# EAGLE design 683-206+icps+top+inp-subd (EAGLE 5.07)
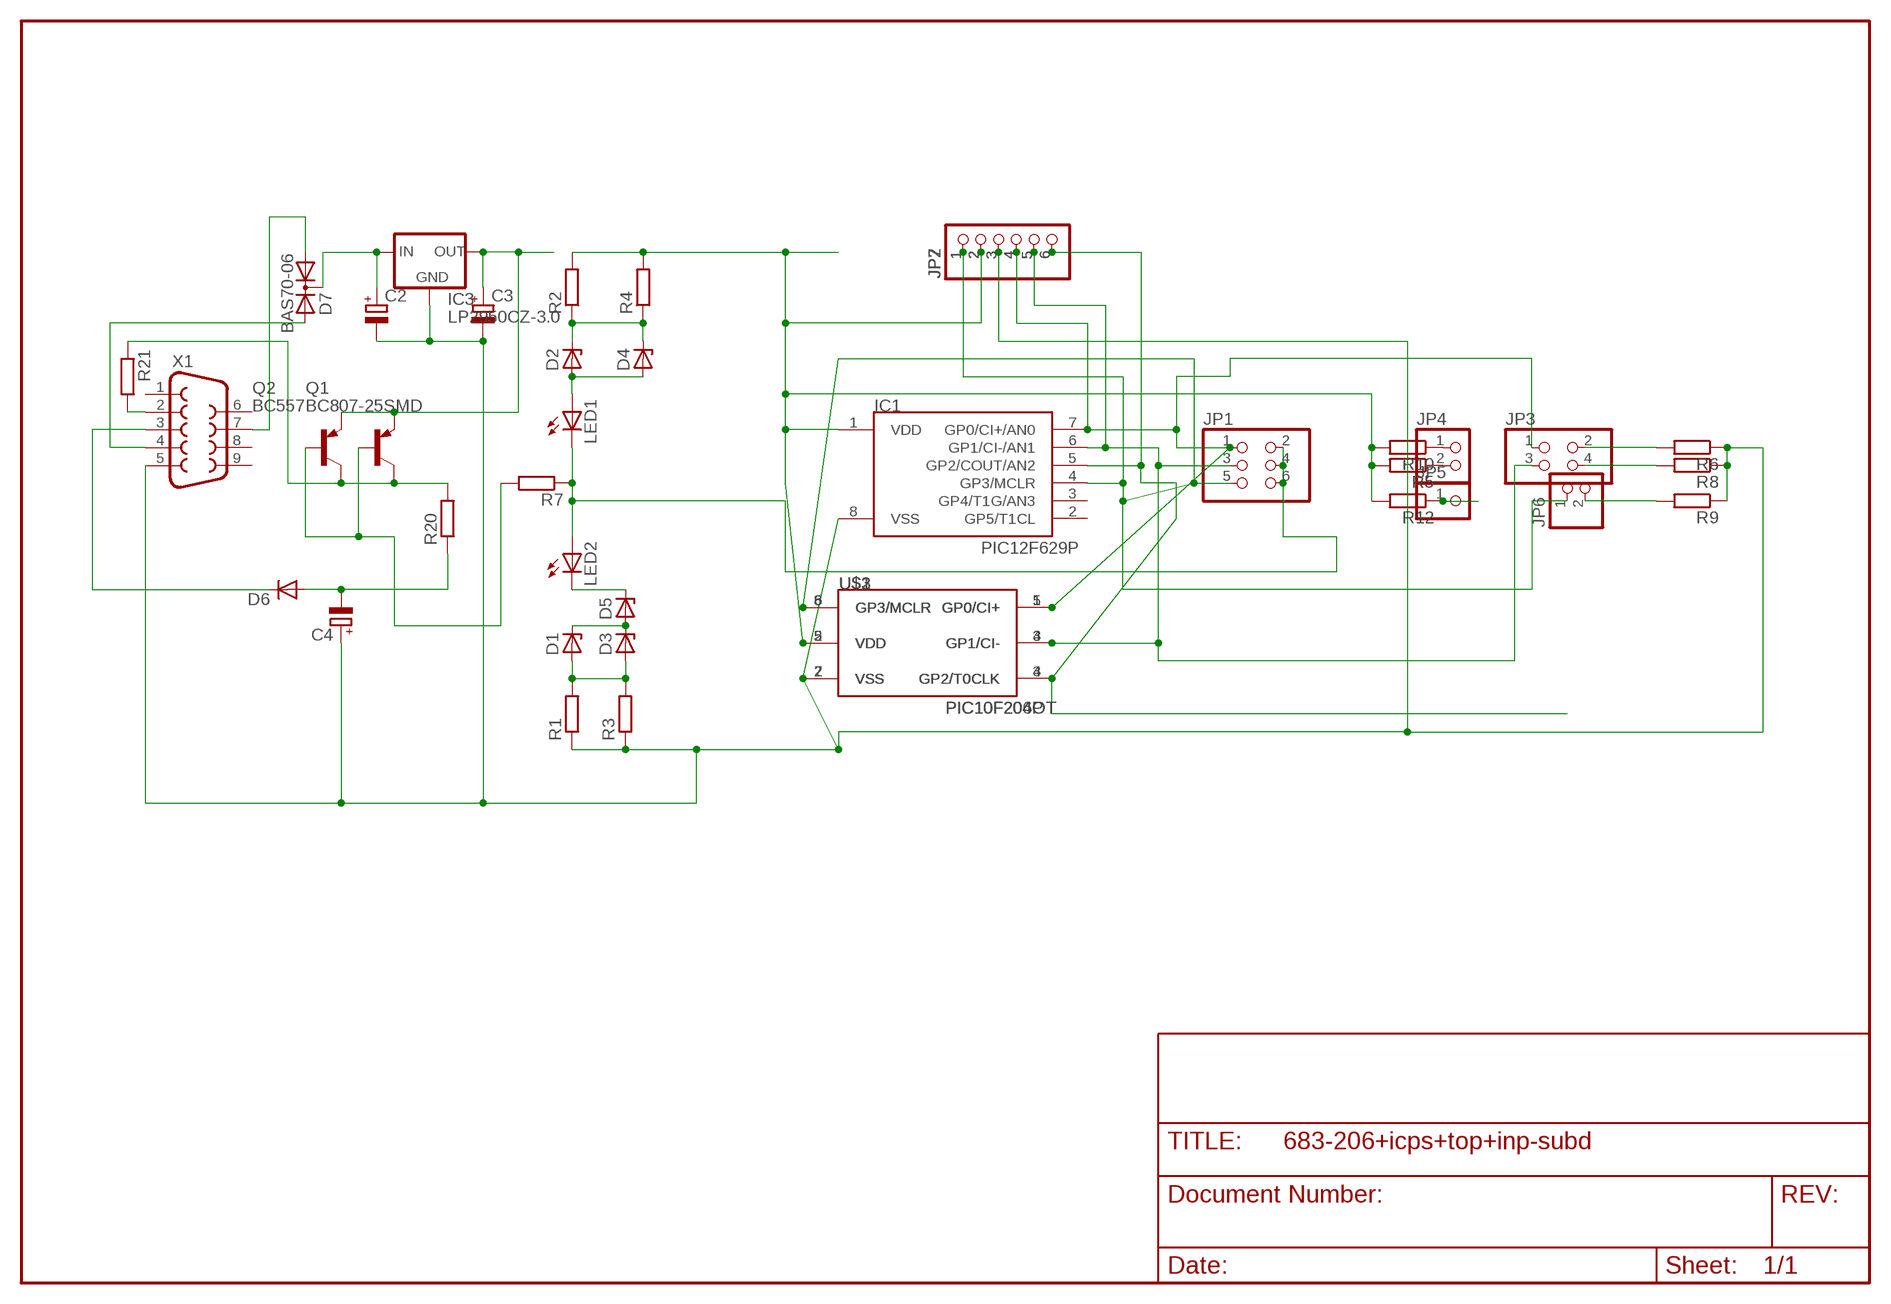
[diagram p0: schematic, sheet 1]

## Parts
C2  CPOL-EUE2-5  [E2-5]
C3  CPOL-EUE2.5-5  [E2,5-5]
C4  CPOL-EUE2.5-5  [E2,5-5]
D1  ZENER-DIODESOT23  [SOT23]
D2  ZENER-DIODESOT23  [SOT23]
D3  ZENER-DIODEZD-2.5  [ZDIO-2.5]
D4  ZENER-DIODEZD-2.5  [ZDIO-2.5]
D5  ZENER-DIODESOT23  [SOT23]
D6  DIODE-D-5  [D-5]
D7  BAS70-06  [SOT23]
IC1  PIC12F629P  [DIL8]
IC3  LP2950CZ-3.0  [TO92]
JP1  PINHD-2X3  [2X03]
JP2  PINHD-1X6  [1X06]
JP3  PINHD-2X2  [2X02]
JP4  PINHD-1X2  [1X02]
JP5  PINHD-1X1  [1X01]
JP6  PINHD-1X2  [1X02]
JP7  PINHD-1X6  [1X06]
LED1  LED5MM  [LED5MM]
LED2  LED5MM  [LED5MM]
Q1  BC807-25SMD  [SOT23-BEC]
Q2  BC557  [TO92-EBC]
R1  R-EU_0204/2V  [0204V]
R2  R-EU_0204/2V  [0204V]
R3  R-EU_R1206  [R1206]
R4  R-EU_R1206  [R1206]
R5  R-EU_R1206  [R1206]
R6  R-EU_R1206  [R1206]
R7  R-EU_R0805  [R0805]
R8  R-EU_R1206  [R1206]
R9  R-EU_R1206  [R1206]
R10  R-EU_R1206  [R1206]
R12  R-EU_R1206  [R1206]
R20  R-EU_R0805  [R0805]
R21  R-EU_R0805  [R0805]
U$1  PIC10F206P  [DIL8]
U$2  PIC10F204OT  [SOT23-6]
U$3  PIC10F204OT  [SOT23-6]
X1  F09H  [F09H]

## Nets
N$1: IC1.6(GP1/CI-/AN1) JP1.3 JP2.5 JP3.3 JP7.5 U$1.4(GP1/CI-) U$2.3(GP1/CI-) U$3.3(GP1/CI-)
N$2: D1.3(C) D3.C D5.1(A)
N$3: D1.1(A) D3.A R1.2 R3.2
N$4: JP1.2 JP1.4 JP1.6 LED1.K(C) LED2.A R7.1
N$5: D7.2(A2) X1.4
N$6: IC1.1(VDD) JP2.2 JP7.2 R2.2 R4.2 R5.2 R10.2 R12.2 U$1.2(VDD) U$2.5(VDD) U$3.5(VDD)
N$7: D2.1(A) D4.A LED1.A
N$8: D2.3(C) D4.C R2.1 R4.1
N$9: IC1.5(GP2/COUT/AN2) JP2.6 JP7.6 U$1.3(GP2/T0CLK) U$2.4(GP2/T0CLK) U$3.4(GP2/T0CLK)
N$10: IC1.4(GP3/MCLR) JP1.5 JP2.1 JP6.1 JP7.1 U$1.8(GP3/MCLR) U$2.6(GP3/MCLR) U$3.6(GP3/MCLR)
N$11: D5.3(C) LED2.K(C)
N$12: Q1.B Q2.B R7.2
N$13: IC1.7(GP0/CI+/AN0) JP1.1 JP2.4 JP3.1 JP7.4 U$1.5(GP0/CI+) U$2.1(GP0/CI+) U$3.1(GP0/CI+)
N$15: JP4.2 R5.1
N$16: JP4.1 R10.1
N$18: JP5.1 R12.1
N$19: D7.1(A1) X1.7
N$22: JP6.2 R9.2
N$24: JP3.4 R8.2
N$25: JP3.2 R6.2
N$33: D6.C X1.3
N$36: Q1.C Q2.C R20.2 R21.1
N$37: C4.- D6.A R20.1
N$38: R21.2 X1.2
N$40: C2.+ D7.3(C) IC3.3(IN)
VDD: C3.+ IC3.1(OUT) Q1.E Q2.E
VSS: C2.- C3.- C4.+ IC1.8(VSS) IC3.2(GND) JP2.3 JP7.3 R1.1 R3.1 R6.1 R8.1 R9.1 U$1.7(VSS) U$2.2(VSS) U$3.2(VSS) X1.5
Unconnected: IC1.2(GP5/T1CL) IC1.3(GP4/T1G/AN3) X1.1 X1.6 X1.8 X1.9

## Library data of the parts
C2-C4 = rcl-2:CPOL-EU: POLARIZED CAPACITOR, European symbol
D1-D5 = diode-1:ZENER-DIODE: Z-Diode
D6 = diode-1:DIODE-: DIODE
D7 = diode-1:BAS70-06: Silicon Schottky Diodes General-purpose diode for high-speed switching
IC1 = microchip-5:PIC12F6*: uPC nW 1k Program Flash memory 2x Timer Comparator 10b A/D converter/ 4xIN
IC3 = v-reg:LP2950?*: Source: http://cache.national.com/ds/LP/LP2950.pdf
JP1 = pinhead:PINHD-2X3: PIN HEADER
JP2 JP7 = pinhead:PINHD-1X6: PIN HEADER
JP3 = pinhead(2):PINHD-2X2: PIN HEADER
JP4 JP6 = pinhead(2):PINHD-1X2: PIN HEADER
JP5 = pinhead(2):PINHD-1X1: PIN HEADER
LED1 LED2 = led:LED: LED
Q1 = transistor-pnp:BC807*: PNP Transistror
Q2 = transistor-pnp:BC557*: PNP Transistror
R1-R10 R12 R20 R21 = rcl-2:R-EU_: RESISTOR, European symbol
U$1-U$3 = microchip-5:PIC10F2*: uPC nW 0,25/0,5k Program Flash memory Comparator
X1 = con-subd:F09: SUB-D

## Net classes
0 default: width 0.3 mm, drill 0.6 mm, clearance 0.2 mm
1 power: width 0.4 mm, drill 0.6 mm, clearance 0.2 mm

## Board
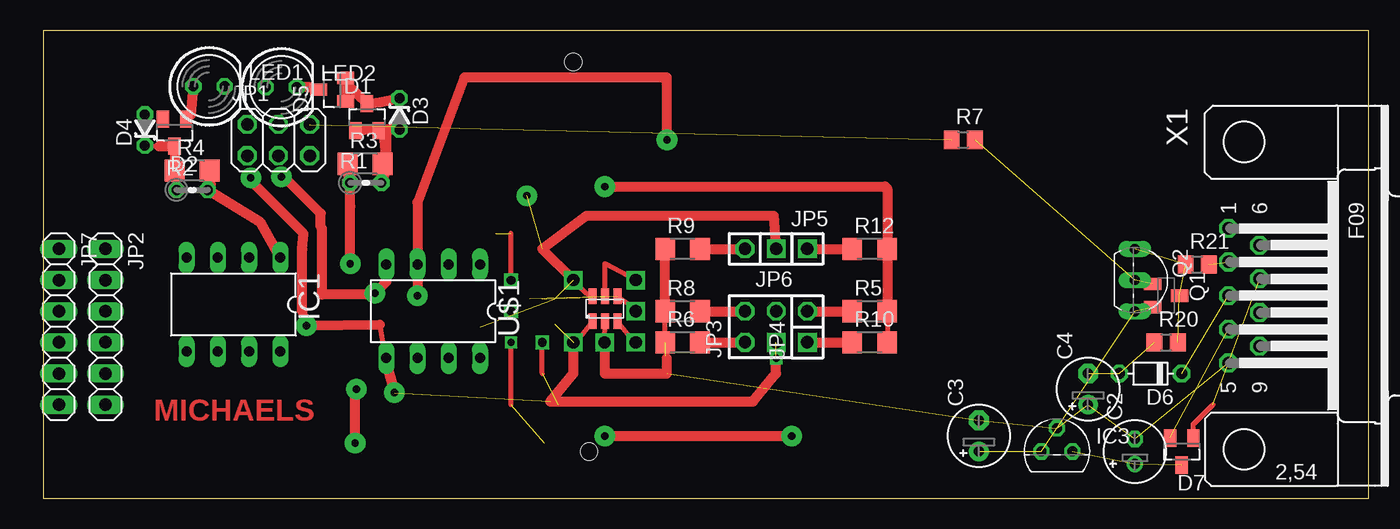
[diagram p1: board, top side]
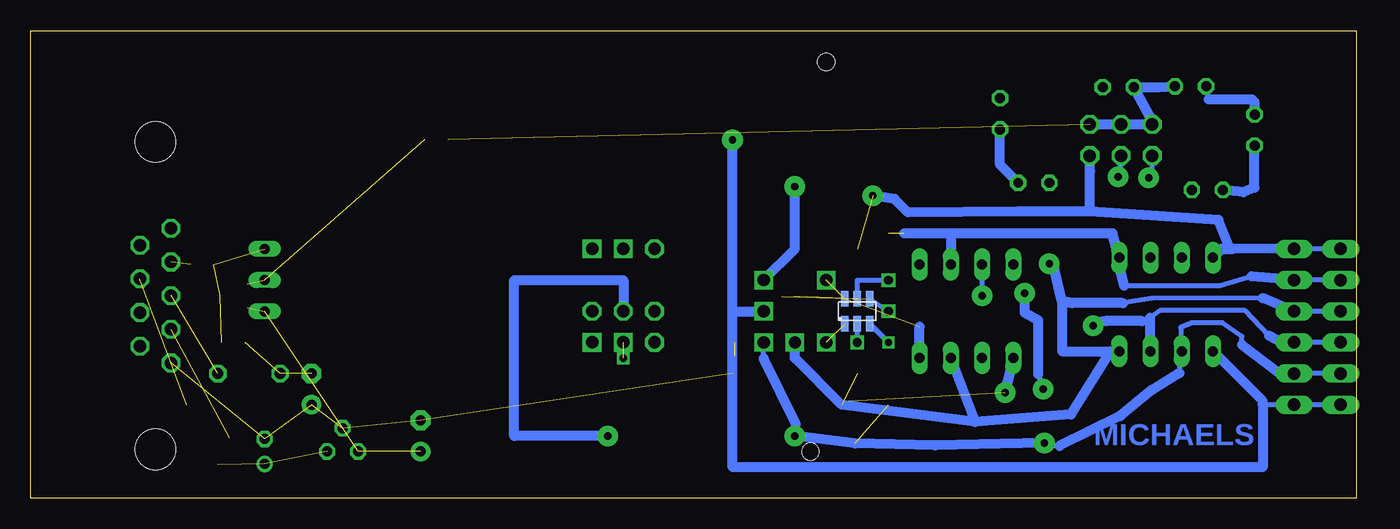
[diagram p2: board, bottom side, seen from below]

Size 107.95 x 38.1 mm. Coordinates in mm from the lower left corner, seen from the top.
Outline: 0,0 107.95,0 107.95,38.1 0,38.1 0,0
Copper layers (1*16): Top 0.035mm / dielectric 1.5mm / Bottom 0.035mm
Design rules "default": minimum track width 10mil, minimum drill 24mil, track to track 8mil, track to pad 8mil, pad to pad 8mil, via to via 8mil, smd to smd 8mil, copper to edge 40mil, drill to drill 8mil, minimum pad ring 10mil, minimum via ring 8mil, stop-mask expansion 4mil, vias tented up to drill 0mil, thermal gap 10mil
Holes 1.4 mm at 44.45,3.81 43.18,35.56

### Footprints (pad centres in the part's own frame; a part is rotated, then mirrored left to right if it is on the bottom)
E2-5 = drill 0.813 pad 1.27 round: + -1.016,0 | drill 0.813 pad 1.27 octagon: - 1.016,0
E2,5-5 = drill 0.813 pad 1.6 round: + -1.27,0 | drill 0.813 pad 1.6 octagon: - 1.27,0
SOT23 = smd 1 x 1.4: 1 -0.95,-1.1; 2 0.95,-1.1; 3 0,1.1
ZDIO-2.5 = drill 0.813 octagon: A 1.27,0; C -1.27,0
D-5 = drill 0.9 octagon: A 2.54,0; C -2.54,0
DIL8 = drill 0.813 long: 1 -3.81,-3.81; 2 -1.27,-3.81; 3 1.27,-3.81; 4 3.81,-3.81; 5 3.81,3.81; 6 1.27,3.81; 7 -1.27,3.81; 8 -3.81,3.81
TO92 = drill 0.813 octagon: 1 -1.27,0; 2 0,1.905; 3 1.27,0
2X03 = drill 1.016 octagon: 1 -2.54,-1.27; 2 -2.54,1.27; 3 0,-1.27; 4 0,1.27; 5 2.54,-1.27; 6 2.54,1.27
1X06 = drill 1.016 long: 1 -6.35,0; 2 -3.81,0; 3 -1.27,0; 4 1.27,0; 5 3.81,0; 6 6.35,0
2X02 = drill 1.016 square: 1 -1.27,-1.27 | drill 1.016 octagon: 2 -1.27,1.27; 3 1.27,-1.27; 4 1.27,1.27
1X02 = drill 1.016 square: 1 -1.27,0 | drill 1.016 octagon: 2 1.27,0
1X01 = drill 1.016 square: 1 0,0
LED5MM = drill 0.813 octagon: A -1.27,0; K 1.27,0
SOT23-BEC = smd 1 x 1.4: B -0.95,-1.1; C 0,1.1; E 0.95,-1.1
TO92-EBC = drill 0.813 long: B 0,-1.27; C -2.54,-1.27; E 2.54,-1.27
0204V = drill 0.813 octagon: 1 -1.27,0; 2 1.27,0
R1206 = smd 1.6 x 1.803: 1 -1.422,0; 2 1.422,0
R0805 = smd 1.3 x 1.5: 1 -0.95,0; 2 0.95,0
SOT23-6 = smd 0.635 x 1.27: 1 -1.016,-1.016; 2 0,-1.016; 3 1.016,-1.016; 4 1.016,1.016; 5 0,1.016; 6 -1.016,1.016
F09H = drill 1.016 octagon: 1 -5.486,-1.27; 2 -2.743,-1.27; 3 0,-1.27; 4 2.743,-1.27; 5 5.486,-1.27; 6 -4.115,1.27; 7 -1.372,1.27; 8 1.372,1.27; 9 4.115,1.27 | hole 3.302: -12.522,0; 12.522,0

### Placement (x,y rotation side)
C2  88.9,3.81 90 top
C3  76.2,5.08 90 top
C4  85.09,8.89 90 top
D1  26.36,31.06 0 top
D2  10.7,29.79 180 top
D3  29.01,31.33 270 top
D4  8.28,30 90 top
D5  23.52,33.29 90 top
D6  90.17,10.16 180 top
D7  92.71,3.81 180 top
IC1  15.49,15.79 180 top
IC3  82.55,3.81 0 top
JP1  19.16,29.19 0 top
JP2  5.08,13.97 270 top
JP3  58.42,13.97 90 top
JP4  62.23,13.97 90 top
JP5  62.23,20.32 0 top
JP6  58.42,20.32 180 top
JP7  1.27,13.97 270 top
LED1  13.5,33.56 0 top
LED2  19.39,33.49 0 top
Q1  91.44,16.51 270 top
Q2  90.17,17.78 270 top
R1  26.27,25.7 0 top
R2  12.13,25.13 0 top
R3  26.22,27.25 0 top
R4  12.13,26.69 0 top
R5  67.31,15.24 0 top
R6  52.07,12.7 0 top
R7  74.93,29.21 0 top
R8  52.07,15.24 0 top
R9  52.07,20.32 0 top
R10  67.31,12.7 0 top
R12  67.31,20.32 0 top
R20  91.44,12.7 0 top
R21  93.98,19.05 0 top
U$1  31.75,15.24 180 top
U$2  45.75,15.44 0 top
U$3  40.64,15.24 0 bottom
X1  97.79,16.51 270 top

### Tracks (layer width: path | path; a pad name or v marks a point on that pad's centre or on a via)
N$1  (via drill 0.6, 0.6 pad 1.68, 1)  (1 unrouted)
  Top 0.406: U$2.3 47.77,13.19 v48.26,12.7 | 25.4,8.6 v25.5,8.9 | v27,16.7 26.9,16.6 | 19.6,26.2 v19.4,26.2 | 22.7,22.01 22.6,22.11 | 38.1,7.62 v38.1,12.7
  Top 0.813: 22.7,22.01 22.7,16.6 26.9,16.6 | v25.4,4.5 25.4,8.6 | v45.72,5.08 v60.96,5.08 | U$1.4 27.94,17.64 v27,16.7 | 19.6,26.2 22.6,23.2 22.6,22.11
  Bottom 0.406: 6.27,10.16 JP2.5 JP7.5 | 9.31,12.5 9.31,13.2 10.91,14.3 13.41,14.3 14.31,13.9 14.31,12.07 IC1.6 14.41,11.79 14.41,10.2 | 48.26,11.43 v48.26,12.7 | v45.72,5.08 45.72,6.03 45.65,6.06 | v25.5,8.9 25.9,10.1 | 24.17,4.26 25.46,4.26 v25.4,4.5 | JP1.3 19.16,26.44 v19.4,26.2 | v38.1,12.7 U$3.3
  Bottom 0.813: 6.27,10.16 9.31,12.5 | 45.65,6.06 48.26,11.43 | 24.17,4.26 19.21,6.7 16.71,8.8 14.41,10.2 | 25.9,10.1 25.9,14.5 27,15.11 v27,16.7 | JP3.3 59.69,17.78 68.58,17.78 68.58,5.08 v60.96,5.08 | v25.4,4.5 34.3,4.3 40.82,4.47 v45.72,5.08
N$2
  Top 0.813: D5.1 24.69,33.8 D1.3 27.4,32.26 D3.C
N$3
  Top 0.813: 27.74,26.56 R3.2 27.94,26.7 R1.2 | D1.1 27.74,30.06 27.94,27.94 27.94,30.06 D3.A
  Bottom 0.813: D3.A 29.01,27.18 R1.2
N$4  (1 unrouted)
  Bottom 0.406: JP1.2 16.62,30.72
  Bottom 0.813: LED1.K 16.11,33.49 LED2.A 16.62,30.72 | JP1.2 JP1.4 JP1.6
N$5  (1 unrouted)
N$6  (via drill 0.6 pad 1.68, 0.7 pad 0.61, 1)  (2 unrouted)
  Top 0.406: U$2.5 45.74,19.13 v48.26,17.78 | 68.58,25.4 68.73,25.25 | R5.2 R10.2 | v38.1,17.78 38.1,21.59
  Top 0.813: IC1.1 17.7,22.47 R2.2 13.65,25.58 R4.2 | 68.73,25.25 R12.2 R5.2 | v45.72,25.4 68.58,25.4
  Bottom 0.406: 8.53,18.08 11.11,17.3 18.91,17.3 | 19.21,18.6 19.21,19.51 IC1.1 | JP7.2 JP2.2 | U$3.5 40.64,17.78 v38.1,17.78
  Bottom 0.813: JP2.2 8.53,18.08 | 18.91,17.3 19.21,18.6 | v48.26,17.78 45.72,20.32 v45.72,25.4 | 33.02,21.59 36.83,21.59 | 33.02,21.59 19.85,21.59 IC1.1 | 33.02,21.59 U$1.2
N$7
  Top 0.813: LED1.A 12.03,31.24 D2.1
  Bottom 0.406: 8.28,32.28 8.5,32.5 | 12.02,32.5 LED1.A
  Bottom 0.813: D4.A 8.28,32.28 | 8.5,32.5 12.02,32.5
N$8
  Top 0.406: 10.67,27.21 R4.1 10.67,26.13 | D4.C 9.44,28.68
  Top 0.813: 10.67,26.13 D2.3 9.44,28.68
  Bottom 0.406: 8.3,28.72 D4.C
  Bottom 0.813: R2.1 9.17,24.93 8.3,25.3 8.3,28.72
N$9  (via drill 0.6 pad 1.68, 0.7 pad 0.61, 1)  (1 unrouted)
  Top 0.406: U$2.4 47.77,15.73 v48.26,15.24
  Top 0.813: v50.8,29.21 50.8,34.29 34.29,34.29 30.48,24.13 U$1.3 v30.48,16.51
  Bottom 0.406: 7.62,7.92 7.62,7.62 JP2.6 JP7.6 | IC1.5 11.28,11.58 11.43,11.43 | U$1.3 v30.48,16.51 | U$3.4 v38.1,15.24
  Bottom 0.813: 50.8,15.24 v48.26,15.24 | 50.8,15.24 50.8,2.54 7.62,2.54 7.62,7.62 | 7.62,7.92 11.28,11.58 | 50.8,15.24 v50.8,29.21
N$10  (via drill 0.6 pad 1.68, 1)  (3 unrouted)
  Top 0.406: U$2.6 44.3,16.66 v43.18,17.78
  Top 0.813: v43.18,17.78 40.64,20.32 44.25,23.03 59.49,23.03 JP6.1
  Bottom 0.406: 10.11,20.3 8.19,20.32 JP2.1 JP7.1
  Bottom 0.813: v39.37,24.66 37.6,24.4 36.51,23.3 27.54,23.37 21.69,23.37 | 21.69,23.37 11.22,22.68 10.32,20.36 JP2.1 | 10.11,20.3 10.98,20.3 IC1.4 10.96,20.32 10.16,20.32 | JP1.5 21.69,26.64 21.69,23.37 | U$1.8 35.56,13.97
N$11
  Top 0.813: LED2.K 21.7,33.49 D5.3
N$12  (2 unrouted)
N$13  (via drill 0.6, 0.6 pad 1.68, 1)  (3 unrouted)
  Top 0.406: U$2.1 43.6,12.92 v43.18,12.7 | 21.1,15.2 22.23,14.07 v21.43,14.07 | 27.4,14.15 27.9,11.2 | 16.9,25.87 v16.9,26.1
  Top 0.813: v21.43,14.07 27.4,14.15 | v59.69,11.43 59.69,10.16 57.82,7.89 41.31,7.89 43.18,10.16 v43.18,12.7 | 21.1,15.2 21.1,20.3 21.2,21.57 16.9,25.87 | 27.9,11.2 v28.6,8.6
  Bottom 0.406: 6.11,12.7 JP2.4 JP7.4 | 7.09,13.24 9.05,15.3 16.01,15.3 16.81,14.7 17.45,14.44 | 16.81,12.03 IC1.7 | 27.9,11.39 U$1.5 | JP1.1 16.62,26.38 v16.9,26.1
  Bottom 0.813: 6.11,12.7 7.09,13.24 | 16.81,14.7 16.81,12.03 | v21.43,14.07 21.46,14.27 20.39,14.44 17.45,14.44 | v28.6,8.6 27.9,11.39
N$15
  Top 0.813: JP4.2 R5.1
N$16
  Top 0.406: R10.1 66.04,12.7
  Top 0.813: JP4.1 R10.1
N$18
  Top 0.813: JP5.1 R12.1
N$19  (1 unrouted)
  Top 0.406: D7.1 93.66,6.03 95.25,7.62
N$22
  Top 0.813: R9.2 JP6.2
N$24
  Top 0.813: R8.2 JP3.4
N$25
  Top 0.813: R6.2 JP3.2
N$33  (1 unrouted)
N$36  (3 unrouted)
N$37  (2 unrouted)
N$38  (1 unrouted)
N$40  (2 unrouted)
VDD  (3 unrouted)
VSS  (via drill 0.6 pad 1.68, 0.7 pad 0.61, 1)  (7 unrouted)
  Top 0.406: v45.72,12.7 U$2.2 | 50.8,11.43 50.65,11.58 | R6.1 R8.1 | 40.64,10.16 v40.64,12.7
  Top 0.813: R3.1 24.69,26.87 R1.1 25,23.8 v25,19.1 | 50.8,11.43 50.8,10.16 45.72,10.16 v45.72,12.7 | R8.1 R9.1
  Bottom 0.406: 7.62,16.31 16.68,16.3 19,15.91 | 24.58,18.68 v25,19.1 | JP7.3 JP2.3 | v40.64,12.7 U$3.2
  Bottom 0.813: JP2.3 7.62,16.31 | 20.01,11.98 IC1.8 | 20.01,11.98 23.97,11.98 23.98,16.09 | 20.01,11.98 23.23,6.82 31.02,6.22 | 31.02,6.22 41.91,7.62 45.72,11.43 v45.72,12.7 | 19,15.91 23.16,15.91 23.37,15.94 23.98,16.09 | 31.02,6.22 U$1.7 | 23.98,16.09 24.58,18.68

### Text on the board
Top: MICHAELS
Bottom: MICHAELS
